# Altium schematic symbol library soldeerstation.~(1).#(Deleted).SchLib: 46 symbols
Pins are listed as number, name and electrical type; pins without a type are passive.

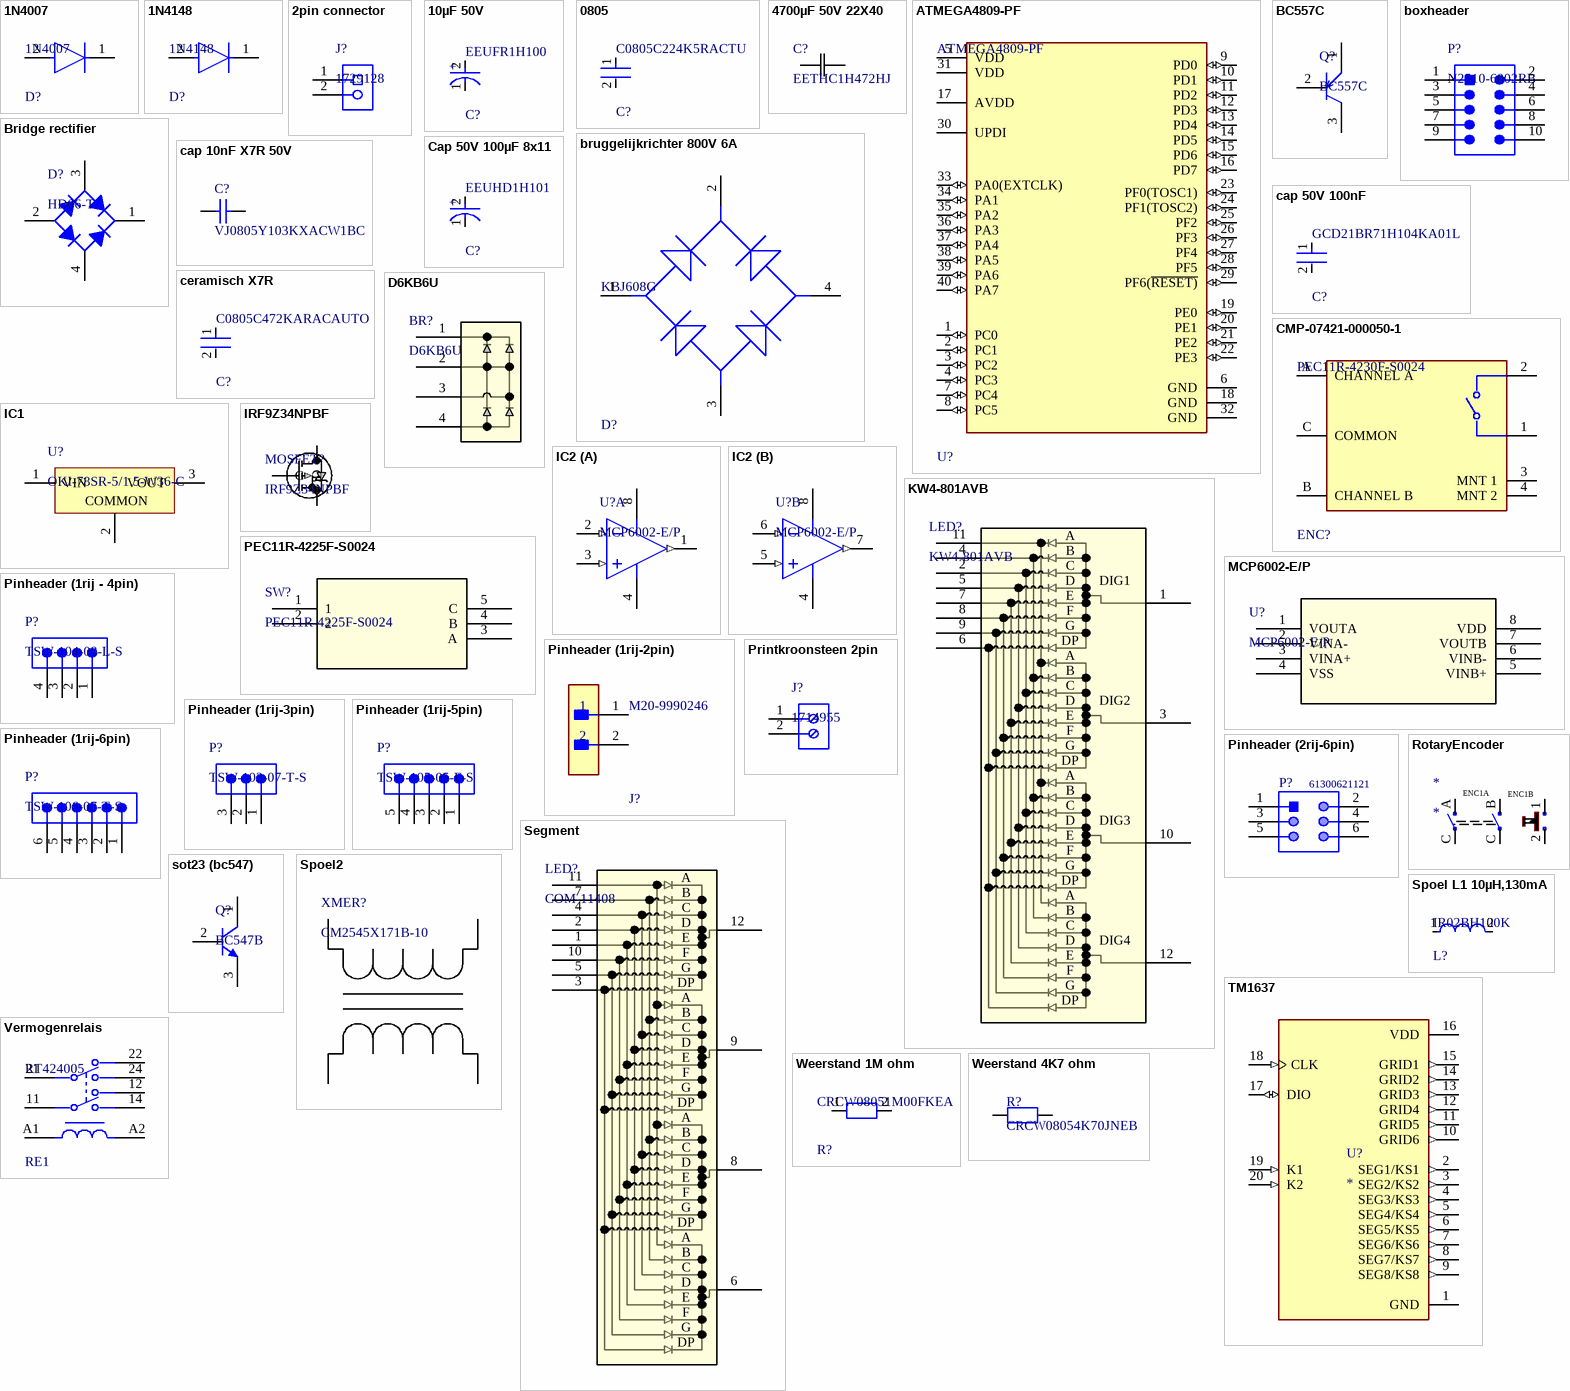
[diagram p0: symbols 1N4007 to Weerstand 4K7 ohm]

## 1N4007
designator D?
Rectifier diode 1000 V 1 A DO-41, ,; Manufacturer: Diotec; Max Surge Forward Current: 27A; Forward Current: 1A; Max Junction Temp: +175°C; Reverse Voltage: 1000V; Value: 15pF; Peak Reverse Current: 5uA
footprint 1N4007
pins: 1 C, 2 A

## 1N4148
designator D?
DIODE GEN PURP 100V 200MA DO35; Forward Voltage: 1V; Max Power Dissipation: 500mW; Max Reverse Current: 5uA; Forward Current: 300mA; Current: 4A; Reverse Recovery Time: 4ns; Element Configuration: Single; Outside Diameter: 1.85mm; Capacitance: 4pF; Polarity: Standard; Max Forward Surge Current (Ifsm): 1A
footprint 1N4148
pins: 1 C, 2 A

## 2pin connector
designator J?, comment 1729128
PCB Terminal Block, 13.5 A, 400 V, 2-Pin THD, RoHS, Bulk; Manufacturer: Phoenix Contact; Package Version: 03/2015; No. of Rows: 1; Pitch: 5.08mm; No. of Positions: 2; Voltage Rating: 400V; Current Rating: 13500mA
footprint 2pin connector (Receptacle, 2-Leads, Body 8.1x10.16mm, Pitch 5.08mm)
pins: 1, 2

## 10µF 50V
designator C?, comment EEUFR1H100
Aluminum Electrolytic Capacitors (Radial Lead Type) 10uF ±20% 50V; Lead Diameter: 0.5mm; Life (Hours): 5000Hour; Impedance: 340mR; Ripple Current (AC): 250mA
footprint cap 10µF 50V
pins: 1 C, 2 A

## 0805
designator C?, comment C0805C224K5RACTU
CAP CER 0.22UF 50V X7R 0805; Manufacturer: KEMET; Value: 0.22 μF; Temperature Coefficient: 30ppm/°C; Material: Ceramic; Tolerance: 0.1
footprint FP-C0805C-DN-IPC_A
pins: 1, 2

## 4700µF 50V 22X40
designator C?, comment EETHC1H472HJ
No Description Available; Mfr_Name: Panasonic; Type: DEV
footprint CAP_PAN_22X40_PAN
pins: 1, 2

## ATMEGA4809-PF
designator U?
IC MCU 8BIT 48KB FLASH 40DIP
footprint ATMEGCPU
footprint 40pin socket
pins: 1 PC0 (io), 2 PC1 (io), 3 PC2 (io), 4 PC3 (io), 5 VDD (power), 6 GND (power), 7 PC4 (io), 8 PC5 (io), 9 PD0 (io), 10 PD1 (io), 11 PD2 (io), 12 PD3 (io), 13 PD4 (io), 14 PD5 (io), 15 PD6 (io), 16 PD7 (io), 17 AVDD (power), 18 GND (power), 19 PE0 (io), 20 PE1 (io), 21 PE2 (io), 22 PE3 (io), 23 PF0(TOSC1) (io), 24 PF1(TOSC2) (io), 25 PF2 (io), 26 PF3 (io), 27 PF4 (io), 28 PF5 (io), 29 PF6(~{RESET)} (io), 30 UPDI, 31 VDD (power), 32 GND (power), 33 PA0(EXTCLK) (io), 34 PA1 (io), 35 PA2 (io), 36 PA3 (io), 37 PA4 (io), 38 PA5 (io), 39 PA6 (io), 40 PA7 (io)

## BC557C
designator Q?
Amplifier Transistor, PNP Silicon, 3-Pin TO-92, Bulk Box; Manufacturer: On Semiconductor; IC Continuous (A): -0.1
footprint BC557C (TO, 3-Leads, Body Dia 4.7mm, Pitch 1.27mm)
pins: 1 C, 2 B, 3 E

## boxheader
designator P?, comment N2510-6002RB
Male Header, Pitch 2.54 mm, 2 x 5 Postion, Height 9.91 mm, Tail Length 2.84 mm, -55 to 105 degC, RoHS, Bulk; PartNumber: N2510; Manufacturer: 3M; Package Version: Rev. M, 08/2014; Rad Hard: No; No. of Rows: 2; Number of Contacts: 10; Pitch: 2.54mm
footprint boxheader (Header, 10-Leads, Body 20.02x8.59mm, Pitch 2.54mm)
pins: 1, 2, 3, 4, 5, 6, 7, 8, 9, 10

## Bridge rectifier
designator D?, comment HD06-T
Glass Passivated Bridge Rectifier, 0.8 A, 600 V, -55 to 150 degC, 4-Pin MiniDIP, RoHS, Tape and Reel; Manufacturer: Diodes Inc; Average Rectified Current-Max: 0.8A; Reverse Voltage-Max [Vrrm]: 600V; Forward Voltage: 1V; Peak Current-Max: 30A; Reverse Current-Max: 5µA; Package Version: 05/2016
footprint FP-KBJ-MFG 800V 6A
pins: 1 K, 2 A, 3 C, 4 C

## bruggelijkrichter 800V 6A
designator D?, comment KBJ608G
BRIDGE RECT 1PHASE 800V 6A KBJ; Manufacturer: Diodes; Max Junction Temp: +150°C; Max Surge Forward Current: 170A; Peak Reverse Current: 5uA; Standoff Height: 3.3mm; Value: 80pF; Forward Current: 3A
footprint FP-KBJ-MFG 800V 6A
pins: 1 +, 2 1 ~, 3 2 ~, 4 -

## cap 10nF X7R 50V
designator C?, comment VJ0805Y103KXACW1BC
Manufacturer: Vitramon
footprint FP-C0805C-DN-IPC_A
pins: 1, 2
1 alternate drawing of the same symbol

## cap 50V 100nF
designator C?, comment GCD21BR71H104KA01L
Chip Multilayer Ceramic Capacitors for Automotive, 0805, 0.10uF, X7R, 15%, 10%, 50V, Grade 1; Capacitance: 100nF
footprint FP-C0805C-DN-IPC_A
pins: 1, 2

## Cap 50V 100µF 8x11
designator C?, comment EEUHD1H101
Aluminum Electrolytic Capacitors (Radial Lead Type) AEC-Q200 Qualified 100uF ±20% 50V; Ripple Current (AC): 180mA; Polarity: Polar; Lead Diameter: 0.6mm; Life (Hours): 1000Hour; Lead/Base Style: Straight
footprint Cap 50V 100µF 8X11
pins: 1 C, 2 A

## ceramisch X7R
designator C?, comment C0805C472KARACAUTO
CAP CER 0805 4.7NF 250V X7R 10%; Manufacturer: KEMET; Material: Ceramic; Value: 4,700 pF; Tolerance: 0.1; Temperature Coefficient: 30ppm/°C
footprint FP-C0805C-DN-IPC_A
pins: 1, 2

## CMP-07421-000050-1
designator ENC?, comment PEC11R-4230F-S0024
ROTARY ENCODER MECHANICAL 24PPR; Detent: Yes; Number of Channels: 2; Output Type: Quadrature; Pulses per Revolution: 24; Hole Diameter: 1.8mm
footprint FP-PEC11R-4230F-S0024-MFG
pins: 1, 2, 3 MNT 1, 4 MNT 2, A CHANNEL A, B CHANNEL B, C COMMON

## D6KB6U
designator BR?
No Description Available; Mfr_Name: Multicomp
footprint SIP4_D6K_MTC
pins: 1, 2, 3, 4

## IC1
designator U?, comment OKI-78SR-5/1.5-W36-C
Non-Isolated DC/DC Converter, 7.5 W, 7 to 36 V, 1.5 A, -40 to 85 degC, 3-Pin THD, RoHS; Manufacturer: Murata; Current - Output (Max): 1.5A; Power (Watts) - Max: 8W; Efficiency: 90.5%; Voltage - Input (Min): 7V; Voltage - Input (Max): 36V; Voltage - Output 1: 5V; Number of Outputs: 1
footprint IC1 (THMT, 3-Leads, Body 10.4x7.6mm)
pins: 1 VIN (power), 2 COMMON (power), 3 VOUT (power)

## IC2
designator U?, comment MCP6002-E/P
None; Slew Rate: 0.6V/µs; Supply Current: 100uA; Power Supply Rejection Ratio (PSRR): 86dB; Input Offset Voltage (Vos): 4.5mV; Input Bias Current: 1pA; Amplifier Type: GENERAL PURPOSE; Unity Gain Bandwidth Product: 1MHz; Number of Circuits: 2; Output Current: 23mA; Operating Supply Voltage: 5.5V; Min Supply Voltage: 1.8V; Common Mode Rejection Ratio: 60dB; Voltage Gain: 112dB; Max Supply Voltage: 6V
footprint IC2 (8-Pin Plastic Dual In-Line Package (PDIP))
footprint 8pin Socket
pins on every part: 4 VSS (power), 8 VDD (power)
part A pins: 1 VOUTA (out), 2 VINA- (in), 3 VINA+ (in)
part B pins: 5 VINB+ (in), 6 VINB- (in), 7 VOUTB (out)

## IRF9Z34NPBF
designator MOSFET?
No Description Available; Mfr_Name: Infineon
footprint IRF
pins: 1 G, 2 D, 3 S

## KW4-801AVB
designator LED?
No Description Available; Mfr_Name: Luckylight Electronics; Type: DEV
footprint KW4801AVB
pins: 1 COMMON_ANODE_1, 2 CATHODE_C, 3 COMMON_ANODE_2, 4 CATHODE_B, 5 CATHODE_D, 6 CATHODE_DP, 7 CATHODE_E, 8 CATHODE_F, 9 CATHODE_G, 10 COMMON_ANODE_3, 11 CATHODE_A, 12 COMMON_ANODE_4

## MCP6002-E/P
designator U?
No Description Available; Mfr_Name: Microchip
footprint PDIP8_300MC_MCH
footprint 8pin Socket
pins: 1 VOUTA, 2 VINA-, 3 VINA+, 4 VSS, 5 VINB+, 6 VINB-, 7 VOUTB, 8 VDD

## PEC11R-4225F-S0024
designator SW?
No Description Available; Mfr_Name: Bourns Electronics
footprint FP-PEC11R-4230F-S0024-MFG
pins: 1, 2, 3 A, 4 B, 5 C

## Pinheader (1rij - 4pin)
designator P?, comment TSW-104-08-L-S
0.025" SQ Post Header, Through-hole, Vertical, -55 to 125 degC, 2.54 mm Pitch, 4-Pin, Male, RoHS; Manufacturer: Samtec; Pitch: 2.54 mm
footprint Pinheader (1rij-4pin) (.025 SQ Post Terminal Strip Assembly, 1x4 Pins, Vertical, 2.54mm Pitch, Male)
pins: 1, 2, 3, 4

## Pinheader (1rij-2pin)
designator J?, comment M20-9990246
CONN HEADER VERT 2POS 2.54MM; Manufacturer: Harwin; Conn Gender: Male; Conn Orientation: Vertical; Number Of Contacts: 2; Current Rating: 3A
footprint Pinheader (1rij-2pin)
pins: 1, 2

## Pinheader (1rij-3pin)
designator P?, comment TSW-103-07-T-S
0.025" SQ Post Header, Through-hole, Vertical, -55 to 105 degC, 2.54 mm Pitch, 3-Pin, Male, RoHS; Manufacturer: Samtec; Pitch: 2.54 mm
footprint Pinheader (1rij-3pin) (.025 SQ Post Terminal Strip Assembly, 1x3 Pins, Vertical, 2.54mm Pitch, Male)
pins: 1, 2, 3

## Pinheader (1rij-5pin)
designator P?, comment TSW-105-05-F-S
0.025" SQ Post Header, Through-hole, Vertical, -55 to 125 degC, 2.54 mm Pitch, 5-Pin, Male, RoHS; Manufacturer: Samtec; Pitch: 2.54 mm
footprint Pinheader (1rij-5pin) (.025 SQ Post Terminal Strip Assembly, 1x5 Pins, Vertical, 2.54mm Pitch, Male)
pins: 1, 2, 3, 4, 5

## Pinheader (1rij-6pin)
designator P?, comment TSW-106-07-T-S
0.025" SQ Post Header, Through-hole, Vertical, -55 to 105 degC, 2.54 mm Pitch, 6-Pin, Male, RoHS; Manufacturer: Samtec; Pitch: 2.54 mm
footprint Pinheader (1rij-6pin) (.025 SQ Post Terminal Strip Assembly, 1x6 Pins, Vertical, 2.54mm Pitch, Male)
pins: 1, 2, 3, 4, 5, 6

## Pinheader (2rij-6pin)
designator P?, comment 61300621121
THT Vertical Pin Header WR-PHD, Pitch 2.54 mm, Dual Row, 6 pins; Manufacturer: Wurth Elektronik; Contact Resistance: 20mOhm; Withstanding Voltage: 500VAC; Pin Number: 6; Gender: Male; Pitch: 2.54mm; Working Voltage: 250VAC; Rated Current: 3A
footprint Pinheader (2rij-6pin) (Pin Header, pitch 2.54 mm, THT, Vertical, dual row, 6p)
pins: 1, 2, 3, 4, 5, 6

## Printkroonsteen 2pin
designator J?, comment 1714955
PC Terminal Block, Pitch 6.35 mm, 1 x 2 Position, Height 21.5 mm, Tail Lenght 5.1 mm, RoHS, Bulk; Manufacturer: Phoenix Contact
footprint Printkroonsteen 2pin (Terminal Block, 2-Leads, Body 12.7x12.5mm, Pitch 6.35mm)
footprint TERM_BLOCK (Female Header, Pitch 5mm, 1 x 2 Position, Height 10mm)
pins: 1, 2

## RotaryEncoder
designator *
footprint FP-PEC11R-4230F-S0024-MFG
pins: 1, 2, A, B, C, C

## Segment
designator LED?, comment COM-11408
No Description Available; Mfr_Name: Sparkfun; Type: DEV
footprint Segment
pins: 1, 2, 3, 4, 5, 6, 7, 8, 9, 10, 11, 12

## sot23 (bc547)
designator Q?, comment BC547B
Amplifier Transistor, NPN Silicon, 3-Pin TO-92, Bulk Box; Manufacturer: On Semiconductor; IC Continuous (A): 0.1; fT Min (MHz): 150
footprint sot23 (TO, 3-Leads, Body Dia 4.7mm, Pitch 1.27mm)
pins: 1 C, 2 B, 3 E

## Spoel2
designator XMER?, comment CM2545X171B-10
No Description Available; Mfr_Name: Laird
footprint spoel2
pins: 1, 2, 3, 4

## Spoel L1 10µH,130mA
designator L?, comment IR02BH100K
IR-2 10 10% B08; Obsolete Part: true; Manufacturer: Vishay Dale; Core Material: Iron; Value: 10uH; Test Frequency: 7.9MHz; Saturation Current: 130mA; Series Resistance: 3.7Ω; Q Factor: 55; Self Resonant Frequency: 50MHz
footprint Spoel L1 10µH,130mA
pins: 1, 2

## TM1637
designator U?
LED Drive Control Special Circuit; MF: Titan Micro Electronics; MP: TM1637
footprint TM1637
footprint DIP20SOCKET
pins: 1 GND (power), 2 SEG1/KS1 (out), 3 SEG2/KS2 (out), 4 SEG3/KS3 (out), 5 SEG4/KS4 (out), 6 SEG5/KS5 (out), 7 SEG6/KS6 (out), 8 SEG7/KS7 (out), 9 SEG8/KS8 (out), 10 GRID6 (out), 11 GRID5 (out), 12 GRID4 (out), 13 GRID3 (out), 14 GRID2 (out), 15 GRID1 (out), 16 VDD (power), 17 DIO (io), 18 CLK (in), 19 K1 (in), 20 K2 (in)

## Vermogenrelais
designator RE1, comment RT424005
RELAY GENERAL PURPOSE DPDT 8A 5V; Manufacturer: TE Connectivity; Coil Power: 403mW; Number Of Contacts: 2; Coil Resistance: 62Ω; Coil Type: Non-Latching
footprint Vermogenrelais
pins: 11, 12, 14, 21, 22, 24, A1, A2

## Weerstand 1M ohm
designator R?, comment CRCW08051M00FKEA
RES Thick Film, 1MΩ, 1%, 0.125W, 100ppm/°C, 0805; Voltage Rating (DC): 150V; Resistance: 1MR; Power Rating: 125mW
footprint Weerstand 1M ohm
pins: 1, 2

## Weerstand 4K7 ohm
designator R?, comment CRCW08054K70JNEB
Manufacturer: Vishay Dale
footprint Weerstand 1M ohm
pins: 1, 2
1 alternate drawing of the same symbol

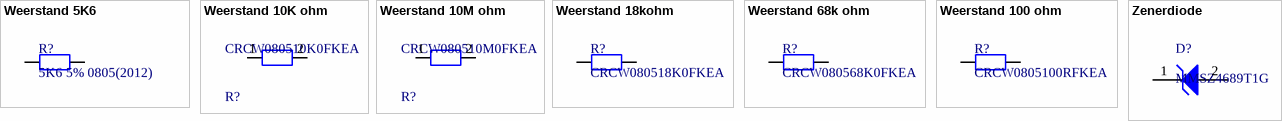
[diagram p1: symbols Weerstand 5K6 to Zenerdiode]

## Weerstand 5K6
designator R?, comment 5K6 5% 0805(2012)
5K6 0.125W 5% 0805 (2012 Metric)  SMD; Value: 5600.00 Ohm; Case-EIA: 0805; Case-Metric: 2012
footprint Weerstand 1M ohm
pins: 1, 2
1 alternate drawing of the same symbol

## Weerstand 10K ohm
designator R?, comment CRCW080510K0FKEA
RES Thick Film, 10kΩ, 1%, 0.125W, 100ppm/°C, 0805; Resistance: 10kR; Voltage Rating (DC): 150V; Power Rating: 125mW
footprint Weerstand 1M ohm
pins: 1, 2

## Weerstand 10M ohm
designator R?, comment CRCW080510M0FKEA
RES Thick Film, 10MΩ, 1%, 0.125W, 100ppm/°C, 0805; Power Rating: 125mW; Voltage Rating (DC): 150V; Tolerance: 5%; Resistance: 10MR
footprint Weerstand 1M ohm
pins: 1, 2

## Weerstand 18kohm
designator R?, comment CRCW080518K0FKEA
Manufacturer: Vishay Dale
footprint Weerstand 1M ohm
pins: 1, 2
1 alternate drawing of the same symbol

## Weerstand 68k ohm
designator R?, comment CRCW080568K0FKEA
Manufacturer: Vishay Dale
footprint Weerstand 1M ohm
pins: 1, 2
1 alternate drawing of the same symbol

## Weerstand 100 ohm
designator R?, comment CRCW0805100RFKEA
Manufacturer: Vishay Dale
footprint Weerstand 1M ohm
pins: 1, 2
1 alternate drawing of the same symbol

## Zenerdiode
designator D?, comment MMSZ4689T1G
Zener Voltage Regulator, 500 mW, 2-Pin SOD-123, Pb-Free, Tape and Reel; Manufacturer: On Semiconductor; VZ Typ (V): 5.1; P Max (W): 0.5
footprint 1N4007
footprint 1N4148
pins: 1 K, 2 A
